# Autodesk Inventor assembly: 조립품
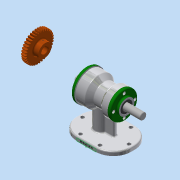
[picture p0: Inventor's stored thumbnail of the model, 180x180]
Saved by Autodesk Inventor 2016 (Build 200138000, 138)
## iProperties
Created: 2020-01
Part Number: 조립품
Material: 일반
Document SubType Name: Assembly
Designer: woori
Author: woori
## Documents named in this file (9)
- C:\Users\woori\Desktop\700104V1020\조립품.iam
- C:\Users\woori\Desktop\700104V1020\본체.ipt
- C:\Users\woori\Desktop\700104V1020\뒤커버.ipt
- C:\Users\woori\Desktop\700104V1020\앞커버.ipt
- C:\Users\woori\Desktop\700104V1020\축.ipt
- C:\Users\woori\Desktop\700104V1020\볼트 M4.ipt
- C:\Users\woori\Desktop\700104V1020\스퍼기어.ipt
- C:\Users\woori\Desktop\700104V1020\오일 실 17 30 8.ipt
- C:\Users\woori\Desktop\700104V1020\오일 실 25 38 8.ipt
